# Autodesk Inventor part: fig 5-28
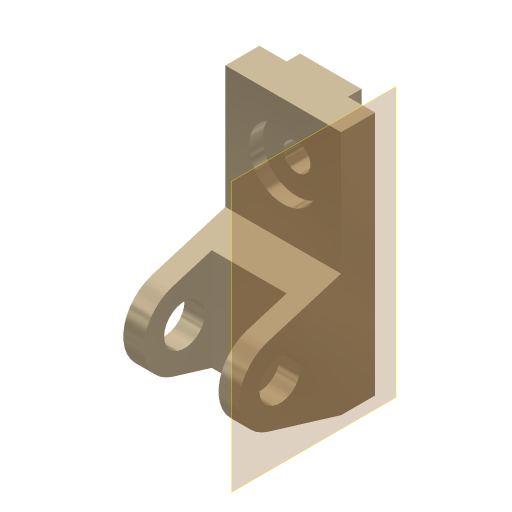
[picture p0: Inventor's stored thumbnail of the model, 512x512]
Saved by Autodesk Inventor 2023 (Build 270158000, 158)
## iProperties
Created: 2001-11
Part Number: fig 5-28
Document SubType Name: Modeling
Designer: Renu Muthoo
Density: 1 g/cm^3
Material: Generic
Appearance: Metal-Titanium (Polished)
Control State: 0
Master: False
Checked Out: False
Shininess: 65.0
Angle Display Precision: 2
Document Length Units: 11269
Document Angle Units: 11279
Document Time Units: 11290
Document Mass Units: 11283
Document Length Units Precision: 3
Document Angle Units Precision: 2
Density: 0.0
Volumn: 0.0
Area: 0.0
PropertySet Name: Model Information
Author: Renu Muthoo
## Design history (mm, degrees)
node "Sketch1"
sketch "Sketch2"
  geometry: L1 (33.257, 104.664)-(33.257, -75.336); L2 (33.257, -75.336)-(8.257, -75.336); L3 (8.257, -75.336)-(-45.451, -59.045); L4 (-45.451, -1.628)-(8.257, 14.664); L5 (8.257, 14.664)-(8.257, 104.664); L6 (8.257, 104.664)-(33.257, 104.664); C1 r 15 at (-36.743, -30.336); A1 r 30 centre (-36.743, -30.336) between (-45.451, -1.628) and (-45.451, -59.045)
  constraints: 12 end point, 2 centre point, 2 equal length, 2 parallel, 2 point on circle, 2 tangent, 1 coincident, 1 perpendicular, 1 vertical
  dimensions: "d0" = 180 distance of L1.start L1.end; "d1" = 30 radius of A1; "d2" = 25 distance of L5.end L1.start; "d3" = 45 distance from line of L2 A1.centre; "d4" = 70 distance from line of L1 A1.centre; "d5" = 30 diameter of C1
extrude "Extrusion1" new body sketch "Sketch2" distance "d6" = 85; taper "d7" = 0 deg
workplane "Work Plane1"
sketch "Sketch3"
  geometry: L1 (15, 62.364)-(70, 62.364); L2 (70, 62.364)-(70, -52.386); L3 (70, -52.386)-(15, -52.386); L4 (15, -52.386)-(15, 62.364); L5 (0, -45)-(0, -28.708) reference
  constraints: 8 end point, 2 parallel, 1 horizontal, 1 perpendicular
  dimensions: "d8" = 55 distance of L1.start L1.end; "d9" = 15 distance between parallel lines of L5 L4
extrude "Extrusion2" cut sketch "Sketch3" distance "d10" = 50; taper "d11" = 0 deg
sketch "Sketch4"
  geometry: L1 (0, 25)-(85, 25) reference; L2 (0, 0)-(0, 25) reference; L3 (20, 25)-(65, 25); L4 (65, 25)-(65, 35); L5 (65, 35)-(20, 35); L6 (20, 35)-(20, 25)
  constraints: 8 end point, 2 parallel, 1 horizontal, 1 perpendicular, 1 point on line
  dimensions: "d12" = 45 distance of L4.end L5.end; "d13" = 10 distance of L3.end L4.end; "d14" = 20 distance between parallel lines of L2 L6
extrude "Extrusion3" join sketch "Sketch4" stored distance "d15" = 50; taper "d16" = 0 deg
sketch "Sketch5"
  geometry: L1 (85, 0)-(85, 90) reference; L2 (0, 90)-(85, 90) reference; 1 further point
  dimensions: "d17" = 42 distance from line of L2 point (42.5, 48); "d18" = 42.5 distance from line of L1 point (42.5, 48)
hole "Hole1" sketch "Sketch5" at (42.5, 48) diameter "d19" = 20; stored, may be unused: countersink angle "d23" = 82 deg, drill point angle "d25" = 118 deg; dims "d20" = 6, "d21" = 50, "d22" = 10, "d24" = 8
workplane "Work Plane4"
body "Solid1"
other parameters: "d26" = 0
